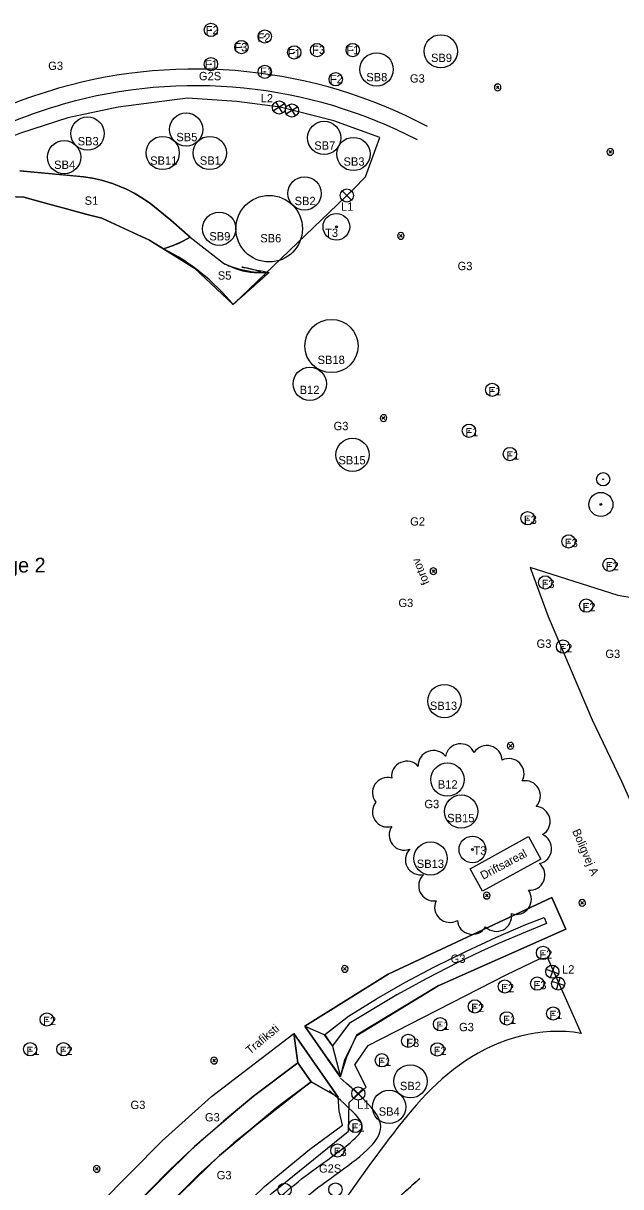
# Model space of a CAD drawing. Extents: x 0 to 512122, y 0 to 6212554.
# Drawn here: x 511504.4 to 511594.1, y 6211506.3 to 6211681 of the extents above; entities that cross this region are included whole.
import ezdxf

# ---------------------------------------------------------------- set-up
doc = ezdxf.new("R2010")
doc.units = 0
for name, color, linetype in [('_G3S_Slået græsser', 7, 'Continuous'), ('_lights', 7, 'Continuous'), ('_Låge L1', 7, 'Continuous'), ('_Låge L2', 7, 'Continuous'), ('_ny fruit trees', 7, 'Continuous'), ('_Paths', 7, 'Continuous'), ('_S1_rabarber', 7, 'Continuous'), ('_S5_spansk kørvel', 7, 'Continuous'), ('_solitaire tree_ K3', 7, 'Continuous'), ('Clouds', 7, 'Continuous'), ('L40 jord udlagt muld og grøft', 7, 'Continuous'), ('MatrikelnummerMaster', 7, 'Continuous'), ('Pumpstation', 7, 'Continuous'), ('Skel', 7, 'Continuous'), ('TV_U_AFM_Symbl_Gul', 7, 'Continuous'), ('TV_U_LYS_Ledn-ror', 7, 'Continuous'), ('TV_U_LYS_Mastenummer', 7, 'Continuous'), ('TV_U_LYS_Nyx330-Trafiksti-x2', 7, 'Continuous')]:
    doc.layers.add(name, color=color, linetype=linetype)

# ---------------------------------------------------------------- blocks, each defined once
blk = doc.blocks.new('SOLITAIRE TREES')
at = {"layer": 'Skel'}
for radius in [2, 0.141]:
    blk.add_circle((0, 0), radius, dxfattribs=at)

msp = doc.modelspace()

# ---------------------------------------------------------------- linework, layer by layer
at = {"layer": '_G3S_Slået græsser'}
msp.add_arc((511599.73, 6211577.45), 18.3, 247.4746, 247.4746, dxfattribs=at)
at = {"layer": '_lights'}
for p, q in [((511575.44, 6211671.6), (511575.84, 6211671.2)), ((511575.84, 6211671.6), (511575.45, 6211671.21)), ((511592.35, 6211661.9), (511592.75, 6211661.51)), ((511592.75, 6211661.9), (511592.36, 6211661.51)), ((511560.9, 6211649.28), (511561.3, 6211648.89)), ((511561.3, 6211649.28), (511560.91, 6211648.89)), ((511558.29, 6211621.94), (511558.69, 6211621.54)), ((511558.69, 6211621.94), (511558.3, 6211621.55)), ((511566.18, 6211598.93), (511565.78, 6211598.53)), ((511565.78, 6211598.92), (511566.17, 6211598.53)), ((511577.37, 6211572.72), (511577.77, 6211572.32)), ((511577.77, 6211572.72), (511577.38, 6211572.33)), ((511574.19, 6211550.21), (511573.79, 6211549.82)), ((511573.79, 6211550.21), (511574.18, 6211549.82)), ((511588.14, 6211549.12), (511588.54, 6211548.72)), ((511588.54, 6211549.12), (511588.15, 6211548.73)), ((511552.88, 6211539.2), (511552.49, 6211538.81)), ((511552.49, 6211539.2), (511552.88, 6211538.8)), ((511533.25, 6211525.43), (511532.85, 6211525.04)), ((511532.85, 6211525.43), (511533.24, 6211525.03)), ((511515.23, 6211509.16), (511515.63, 6211508.76)), ((511515.63, 6211509.16), (511515.24, 6211508.77))]:
    msp.add_line(p, q, dxfattribs=at)
for centre, start, end in [((511575.64, 6211671.4), 315.5636, 315), ((511575.64, 6211671.4), 315, 315.5636), ((511592.55, 6211661.7), 315.5636, 315), ((511592.55, 6211661.7), 315, 315.5636), ((511561.1, 6211649.08), 315.5636, 315), ((511561.1, 6211649.08), 315, 315.5636), ((511558.49, 6211621.74), 315.5636, 315), ((511558.49, 6211621.74), 315, 315.5636), ((511565.98, 6211598.73), 315.5636, 315), ((511565.98, 6211598.73), 315, 315.5636), ((511577.57, 6211572.52), 315.5636, 315), ((511577.57, 6211572.52), 315, 315.5636), ((511573.99, 6211550.01), 315.5636, 315), ((511573.99, 6211550.01), 315, 315.5636), ((511588.34, 6211548.92), 315.5636, 315), ((511588.34, 6211548.92), 315, 315.5636), ((511552.68, 6211539), 315.5636, 315), ((511552.68, 6211539), 315, 315.5636), ((511533.05, 6211525.23), 315.5636, 315), ((511533.05, 6211525.23), 315, 315.5636), ((511515.43, 6211508.96), 315.5636, 315), ((511515.43, 6211508.96), 315, 315.5636)]:
    msp.add_arc(centre, 0.5, start, end, dxfattribs=at)
at = {"layer": '_Låge L1'}
for p, q in [((511553.69, 6211655.85), (511552.29, 6211654.45)), ((511552.29, 6211655.85), (511553.69, 6211654.45)), ((511555.41, 6211521), (511554.01, 6211519.6)), ((511554.01, 6211521), (511555.41, 6211519.6))]:
    msp.add_line(p, q, dxfattribs=at)
for centre in [(511552.99, 6211655.15), (511554.71, 6211520.3)]:
    msp.add_circle(centre, 0.989, dxfattribs=at)
at = {"layer": '_Låge L2'}
for p, q in [((511543.65, 6211668.9), (511541.97, 6211667.86)), ((511542.29, 6211669.22), (511543.33, 6211667.54)), ((511545.59, 6211668.44), (511543.91, 6211667.4)), ((511544.23, 6211668.76), (511545.27, 6211667.08)), ((511584.15, 6211539.53), (511583.52, 6211537.65)), ((511584.77, 6211538.28), (511582.9, 6211538.9)), ((511585.04, 6211537.74), (511584.42, 6211535.86)), ((511585.67, 6211536.49), (511583.79, 6211537.11))]:
    msp.add_line(p, q, dxfattribs=at)
for centre in [(511542.81, 6211668.38), (511544.75, 6211667.92), (511583.84, 6211538.59), (511584.73, 6211536.8)]:
    msp.add_circle(centre, 0.989, dxfattribs=at)
at = {"layer": '_ny fruit trees'}
for centre, radius in [((511532.59, 6211680.02), 1), ((511532.59, 6211680.02), 0.0426), ((511540.67, 6211679.04), 1), ((511540.67, 6211679.04), 0.0426), ((511537.16, 6211677.44), 1), ((511537.16, 6211677.44), 0.0426), ((511545.1, 6211676.65), 1), ((511548.52, 6211677), 1), ((511548.52, 6211677), 0.0426), ((511553.87, 6211677), 1), ((511553.87, 6211677), 0.0426), ((511532.59, 6211674.88), 1), ((511545.1, 6211676.65), 0.0426), ((511532.59, 6211674.88), 0.0426), ((511540.67, 6211673.73), 1), ((511540.67, 6211673.73), 0.0426), ((511551.32, 6211672.61), 1), ((511551.32, 6211672.61), 0.0426), ((511574.82, 6211625.97), 1), ((511574.82, 6211625.97), 0.0426), ((511571.33, 6211619.83), 1), ((511571.33, 6211619.83), 0.0426), ((511577.48, 6211616.33), 1), ((511577.48, 6211616.33), 0.0426), ((511591.48, 6211612.54), 1), ((511591.48, 6211612.54), 0.0426), ((511580.14, 6211606.69), 1), ((511580.14, 6211606.69), 0.0426), ((511586.29, 6211603.2), 1), ((511586.29, 6211603.2), 0.0426), ((511592.43, 6211599.71), 1), ((511592.43, 6211599.71), 0.0426), ((511582.79, 6211597.05), 1), ((511582.79, 6211597.05), 0.0426), ((511588.94, 6211593.56), 1), ((511588.94, 6211593.56), 0.0426), ((511585.45, 6211587.41), 1), ((511585.45, 6211587.41), 0.0426), ((511582.45, 6211541.41), 1), ((511582.45, 6211541.41), 0.0426), ((511576.72, 6211536.36), 1), ((511581.58, 6211536.79), 1), ((511576.72, 6211536.36), 0.0426), ((511581.58, 6211536.79), 0.0426), ((511572.22, 6211533.37), 1), ((511507.94, 6211531.41), 1), ((511572.22, 6211533.37), 0.0426), ((511577, 6211531.58), 1), ((511583.97, 6211532.31), 1), ((511583.97, 6211532.31), 0.0426), ((511507.94, 6211531.41), 0.0426), ((511566.99, 6211530.7), 1), ((511566.99, 6211530.7), 0.0426), ((511577, 6211531.58), 0.0426), ((511562.22, 6211528.2), 1), ((511505.44, 6211526.94), 1), ((511505.44, 6211526.94), 0.0426), ((511510.44, 6211526.94), 1), ((511510.44, 6211526.94), 0.0426), ((511562.22, 6211528.2), 0.0426), ((511566.58, 6211526.91), 1), ((511566.58, 6211526.91), 0.0426), ((511558.25, 6211525.28), 1), ((511558.25, 6211525.28), 0.0426), ((511554.25, 6211515.42), 1), ((511554.25, 6211515.42), 0.0426), ((511551.58, 6211511.73), 1), ((511551.58, 6211511.73), 0.0426), ((511543.64, 6211505.83), 1), ((511551.28, 6211505.87), 1)]:
    msp.add_circle(centre, radius, dxfattribs=at)
at = {"layer": '_Paths'}
for centre, radius, start, end in [((511530.28, 6211599.47), 74.68, 62.1867, 105.9873), ((511530.83, 6211597.57), 76.66, 105.9873, 117.7388), ((511530.28, 6211599.47), 72.18, 62.5002, 105.9889), ((511530.83, 6211597.57), 74.16, 105.9889, 117.6767)]:
    msp.add_arc(centre, radius, start, end, dxfattribs=at)
for points in [[(511533.83, 6211491.3), (511535.62, 6211493.43), (511540.82, 6211499.61), (511548.51, 6211506.42), (511560.79, 6211514.38), (511556.94, 6211518.3), (511552.05, 6211522.6)], [(511531.91, 6211492.91), (511533.7, 6211495.04), (511539.03, 6211501.36), (511546.99, 6211508.41), (511556.86, 6211514.81), (511555.22, 6211516.48), (511550.4, 6211520.72)]]:
    msp.add_open_spline(points, degree=3, dxfattribs=at)
at = {"layer": '_S1_rabarber'}
for points in [[(511503.91, 6211658.84), (511512.53, 6211658.04), (511513.47, 6211657.95), (511514.8, 6211657.74), (511516.14, 6211657.45), (511517.81, 6211656.96), (511518.83, 6211656.57), (511519.91, 6211656.1), (511521.06, 6211655.51), (511522.47, 6211654.68), (511523.56, 6211653.91), (511526.54, 6211651.43), (511529.47, 6211648.88), (511528.45, 6211648.34), (511528.16, 6211648.19), (511526.89, 6211647.66), (511525.45, 6211647.16), (511523.82, 6211648.17), (511523.38, 6211648.45), (511519.78, 6211650.09), (511516.18, 6211651.73), (511513.82, 6211652.37), (511510.34, 6211653.31), (511508.07, 6211653.93), (511504.51, 6211654.89), (511503.34, 6211654.98)], [(511528.45, 6211648.34), (511529.47, 6211648.88), (511526.54, 6211651.43), (511523.56, 6211653.91), (511522.47, 6211654.68), (511521.06, 6211655.51), (511519.91, 6211656.1), (511518.83, 6211656.57), (511517.81, 6211656.96), (511516.14, 6211657.45), (511514.8, 6211657.74), (511513.47, 6211657.95), (511503.91, 6211658.84)], [(511503.34, 6211654.98), (511504.51, 6211654.89), (511508.07, 6211653.93), (511510.34, 6211653.31), (511513.82, 6211652.37), (511516.18, 6211651.73), (511523.38, 6211648.45), (511523.82, 6211648.17), (511525.45, 6211647.16), (511526.89, 6211647.66), (511527.75, 6211648.02)]]:
    msp.add_lwpolyline(points, dxfattribs=at)
msp.add_arc((511519.16, 6211667.38), 21.18, 293.9173, 296.0104, dxfattribs=at)
at = {"layer": '_S5_spansk kørvel'}
msp.add_lwpolyline([(511528.45, 6211648.34), (511529.47, 6211648.88), (511534.47, 6211644.98)], dxfattribs=at)
msp.add_lwpolyline([(511528.45, 6211648.34), (511529.47, 6211648.88), (511534.47, 6211644.98)], dxfattribs=at)
for centre, radius, start, end in [((511519.16, 6211667.38), 21.18, 287.3435, 296.0104), ((511519.16, 6211667.38), 21.18, 287.3435, 296.0104), ((511510.3, 6211617.56), 33.27, 39.6315, 62.8574), ((511510.3, 6211617.56), 33.27, 39.6315, 62.8574), ((512757.67, 6210270.09), 1834.66, 131.5276, 131.75358), ((512757.67, 6210270.09), 1834.66, 131.5276, 131.75358)]:
    msp.add_arc(centre, radius, start, end, dxfattribs=at)
for points in [[(511534.47, 6211644.98), (511536.61, 6211644.07), (511539.36, 6211643.58), (511541.33, 6211643.58), (511534.47, 6211644.98), (511541.33, 6211643.58)], [(511534.47, 6211644.98), (511535.17, 6211644.65), (511536.72, 6211643.91), (511539.09, 6211643.53), (511540.67, 6211643.57), (511541.33, 6211643.58)]]:
    msp.add_open_spline(points, degree=3, dxfattribs=at)
at = {"layer": '_solitaire tree_ K3'}
for radius in [1.81, 0.127]:
    msp.add_circle((511591.14, 6211608.76), radius, dxfattribs=at)
at = {"layer": 'Clouds'}
for centre, start, end in [((511570.05, 6211570.54), 25.2077, 170.2077), ((511574.02, 6211570.27), 2.0157, 147.0157), ((511565.99, 6211569.54), 37.6761, 182.6761), ((511577.32, 6211568.31), 331.608, 116.608), ((511562, 6211567.92), 41.3523, 186.3523), ((511559.11, 6211565.48), 74.1952, 219.1952), ((511579.78, 6211564.99), 316.3178, 101.3178), ((511559.12, 6211562.6), 140.8408, 285.8408), ((511581.24, 6211561.14), 300.1916, 85.1916), ((511561.62, 6211559.11), 145.6596, 290.6596), ((511581.47, 6211557.08), 281.4375, 66.4375), ((511564.07, 6211555.4), 135.9748, 280.9748), ((511580.45, 6211553.1), 264.8625, 49.8625), ((511566.06, 6211551.49), 133.096, 278.096), ((511578.42, 6211549.47), 251.5454, 36.5454), ((511568.45, 6211548.27), 154.9974, 299.9974), ((511571.86, 6211546.47), 184.528, 329.528), ((511575.45, 6211546.92), 224.7551, 9.7551)]:
    msp.add_arc(centre, 2.28, start, end, dxfattribs=at)
at = {"layer": 'L40 jord udlagt muld og grøft'}
for points in [[(511585.89, 6211544.95), (511566.7, 6211536.46), (511554.44, 6211529.04), (511552.92, 6211525.74), (511551.99, 6211522.79), (511549.8, 6211525.95), (511546.66, 6211530.43), (511559.18, 6211538.24), (511583.79, 6211549.72)], [(511583.79, 6211549.72), (511559.18, 6211538.24), (511546.66, 6211530.43), (511549.8, 6211525.95), (511552.02, 6211522.81), (511552.71, 6211525.38), (511554.49, 6211529.02), (511566.7, 6211536.46), (511585.89, 6211544.95)], [(511582.63, 6211546.75), (511582.99, 6211545.81), (511579.82, 6211544.54), (511575.77, 6211542.81), (511573.1, 6211541.6), (511569.57, 6211539.91), (511565.01, 6211537.58), (511560.5, 6211535.11), (511553.32, 6211530.82), (511550.83, 6211527.45), (511549.66, 6211529.1), (511553.25, 6211531.93), (511557.45, 6211534.49), (511561.72, 6211536.94), (511566.06, 6211539.26), (511570.95, 6211541.69), (511575.37, 6211543.72), (511579.89, 6211545.65)], [(511546.66, 6211530.43), (511549.67, 6211529.11), (511550.85, 6211527.41), (511552.03, 6211522.78)], [(511519.91, 6211502.22), (511515.82, 6211503.61), (511525.25, 6211513.18), (511532.69, 6211519.82), (511545.02, 6211529.29), (511545.61, 6211524.88), (511539, 6211519.89), (511530.1, 6211512.31)], [(511545.02, 6211529.29), (511551.71, 6211519.74), (511547.65, 6211522.04), (511545.61, 6211524.88)], [(511519.91, 6211502.22), (511526.42, 6211508.85), (511529.16, 6211511.45), (511534.45, 6211516.15), (511539, 6211519.89), (511545.61, 6211524.88), (511547.65, 6211522.04), (511542.47, 6211518.17), (511533.87, 6211511), (511522.58, 6211499.95)], [(511525.32, 6211495.05), (511526.64, 6211494.9), (511528.4, 6211494.46), (511540.64, 6211506.35), (511547.4, 6211511.86), (511552.32, 6211515.55), (511551.86, 6211517.68), (511551.71, 6211519.73), (511547.63, 6211522.03), (511536.03, 6211512.89), (511531.05, 6211508.43), (511522.58, 6211499.95)]]:
    msp.add_lwpolyline(points, close=True, dxfattribs=at)
for points in [[(511546.66, 6211530.43), (511549.67, 6211529.11), (511550.85, 6211527.41), (511552.03, 6211522.78), (511546.66, 6211530.43)], [(511545.61, 6211524.88), (511547.65, 6211522.04), (511551.71, 6211519.74), (511545.02, 6211529.29), (511545.61, 6211524.88)], [(511519.91, 6211502.22), (511522.58, 6211499.95), (511533.87, 6211511), (511542.47, 6211518.17), (511547.65, 6211522.04), (511545.61, 6211524.88), (511539, 6211519.89), (511534.45, 6211516.15), (511529.16, 6211511.45), (511526.42, 6211508.85), (511519.91, 6211502.22), (511522.58, 6211499.95)]]:
    msp.add_lwpolyline(points, dxfattribs=at)
at = {"layer": 'MatrikelnummerMaster'}
msp.add_lwpolyline([(511553.97, 6211656.1), (511555.79, 6211657.96), (511557.93, 6211663.87), (511551.03, 6211666.35), (511543, 6211668.4), (511536.48, 6211669.29), (511529.07, 6211669.77), (511518.64, 6211668.43), (511511.1, 6211666.82), (511503.97, 6211664.54), (511497.17, 6211661.84), (511493.04, 6211660.13), (511486.68, 6211657.15), (511484.32, 6211654.41), (511495.49, 6211655.44), (511504.51, 6211654.89), (511516.18, 6211651.73), (511523.38, 6211648.45), (511530.14, 6211644.26), (511535.92, 6211638.78)], close=True, dxfattribs=at)
msp.add_lwpolyline([(511519.3, 6211478.52), (511512.13, 6211482.26), (511517.84, 6211488.88), (511521.98, 6211493.75), (511526.06, 6211494.09), (511530.02, 6211493.42), (511541.67, 6211505.27), (511553.25, 6211514.63), (511553.34, 6211518.92), (511555.87, 6211521.24), (511554.18, 6211524.58), (511556.19, 6211527.5), (511577, 6211538.18), (511581.94, 6211540.5), (511583.12, 6211540.67), (511588.16, 6211529.31)], dxfattribs=at)
msp.add_open_spline([(511588.16, 6211529.31), (511582.04, 6211530.43), (511569.5, 6211526.54), (511558.5, 6211512.66), (511548.44, 6211498.44), (511543.23, 6211488.47), (511531.73, 6211479.28), (511527.73, 6211474.95), (511588.16, 6211529.31), (511527.73, 6211474.95)], degree=3, dxfattribs=at)
at = {"layer": 'Pumpstation'}
msp.add_lwpolyline([(511571.49, 6211554.05), (511580.27, 6211558.87), (511582.1, 6211555.5), (511573.34, 6211550.69), (511571.49, 6211554.05)], dxfattribs=at)
at = {"layer": 'TV_U_LYS_Mastenummer'}
for centre, radius in [((511567.1, 6211676.81), 2.5), ((511567.1, 6211676.81), 2.5), ((511557.46, 6211674.09), 2.5), ((511557.46, 6211674.09), 2.5), ((511514.06, 6211664.45), 2.5), ((511514.06, 6211664.45), 2.5), ((511528.87, 6211665.07), 2.5), ((511528.87, 6211665.07), 2.5), ((511549.59, 6211663.8), 2.5), ((511549.59, 6211663.8), 2.5), ((511510.53, 6211660.91), 2.5), ((511510.53, 6211660.91), 2.5), ((511525.34, 6211661.54), 2.5), ((511525.34, 6211661.54), 2.5), ((511532.41, 6211661.54), 2.5), ((511532.41, 6211661.54), 2.5), ((511553.98, 6211661.39), 2.5), ((511553.98, 6211661.39), 2.5), ((511546.64, 6211655.47), 2.5), ((511546.64, 6211655.47), 2.5), ((511541.33, 6211650.17), 5), ((511541.33, 6211650.17), 5), ((511533.83, 6211650.17), 2.5), ((511533.83, 6211650.17), 2.5), ((511550.68, 6211632.55), 4), ((511550.68, 6211632.55), 4), ((511547.42, 6211626.87), 2.5), ((511547.42, 6211626.87), 2.5), ((511553.85, 6211616.21), 2.5), ((511553.85, 6211616.21), 2.5), ((511567.64, 6211579.23), 2.5), ((511567.64, 6211579.23), 2.5), ((511568.1, 6211567.43), 2.5), ((511568.1, 6211567.43), 2.5), ((511570.16, 6211562.64), 2.5), ((511565.57, 6211555.59), 2.5), ((511562.53, 6211522.12), 2.5), ((511562.53, 6211522.12), 2.5), ((511559.33, 6211518.28), 2.5), ((511559.33, 6211518.28), 2.5)]:
    msp.add_circle(centre, radius, dxfattribs=at)
at = {"layer": 'TV_U_LYS_Nyx330-Trafiksti-x2'}
msp.add_lwpolyline([(511597.63, 6211559.52), (511613.16, 6211564.28), (511614.77, 6211563.81), (511623.67, 6211565.57), (511625.54, 6211567.12), (511626.88, 6211569.29), (511627.71, 6211571.47), (511628.18, 6211574.42), (511628.13, 6211576.38), (511625.9, 6211578.04), (511621.09, 6211580.99), (511612.59, 6211585.69), (511610.51, 6211589.45), (511606.94, 6211592.12), (511604.04, 6211593.64), (511600.52, 6211593.88), (511593.75, 6211595.09), (511580.53, 6211599.31), (511583.21, 6211591.92), (511589.82, 6211576.39), (511594.25, 6211567.21)], close=True, dxfattribs=at)

# ---------------------------------------------------------------- block references
at = {"layer": 'Skel'}
for p in [(511551.42, 6211650.46), (511571.84, 6211556.94)]:
    msp.add_blockref('SOLITAIRE TREES', p, dxfattribs=at)

# ---------------------------------------------------------------- texts
at = {"layer": 'TV_U_AFM_Symbl_Gul'}
for s, p in [('F2', (511531.8, 6211679.36)), ('F2', (511539.58, 6211678.24)), ('F3', (511536.1, 6211676.8)), ('F1', (511544.13, 6211675.89)), ('F3', (511547.78, 6211676.4)), ('F1', (511552.91, 6211676.38)), ('G3', (511508.15, 6211674.01)), ('F1', (511531.67, 6211674.23)), ('SB9', (511565.63, 6211675.21)), ('G2S', (511530.78, 6211672.47)), ('F1', (511539.97, 6211673.13)), ('SB8', (511555.91, 6211672.31)), ('F2', (511550.44, 6211672.02)), ('G3', (511562.46, 6211672.11)), ('L2', (511540.05, 6211669.14)), ('SB3', (511512.57, 6211662.69)), ('SB5', (511527.39, 6211663.31)), ('SB7', (511548.1, 6211662.04)), ('SB4', (511509.04, 6211659.15)), ('SB11', (511523.46, 6211659.78)), ('SB1', (511530.92, 6211659.78)), ('SB3', (511552.49, 6211659.63)), ('S1', (511513.62, 6211653.76)), ('SB2', (511545.15, 6211653.71)), ('L1', (511552.11, 6211652.86)), ('SB9', (511532.35, 6211648.41)), ('SB6', (511539.99, 6211648.12)), ('T3', (511549.72, 6211648.93)), ('G3', (511569.62, 6211643.94)), ('S5', (511533.62, 6211642.52)), ('SB18', (511548.6, 6211629.85)), ('B12', (511545.9, 6211625.34)), ('F1', (511574.27, 6211625.13)), ('G3', (511551, 6211619.91)), ('F1', (511570.78, 6211618.98)), ('SB15', (511551.73, 6211614.78)), ('F1', (511576.93, 6211615.49)), ('G2', (511562.5, 6211605.58)), ('F3', (511579.58, 6211605.84)), ('F3', (511585.73, 6211602.35)), ('F2', (511591.88, 6211598.86)), ('F3', (511582.24, 6211596.2)), ('G3', (511560.74, 6211593.35)), ('F2', (511588.39, 6211592.71)), ('G3', (511581.48, 6211587.23)), ('F2', (511584.9, 6211586.56)), ('G3', (511591.81, 6211585.7)), ('SB13', (511565.46, 6211577.9)), ('B12', (511566.65, 6211566.09)), ('G3', (511564.64, 6211563.14)), ('SB15', (511568.06, 6211561.04)), ('T3', (511571.99, 6211556.16)), ('SB13', (511563.5, 6211554.17)), ('G3', (511568.58, 6211539.91)), ('F2', (511581.89, 6211540.56)), ('L2', (511585.3, 6211538.31)), ('F2', (511576.17, 6211535.51)), ('F3', (511581.02, 6211535.95)), ('F2', (511571.67, 6211532.52)), ('F1', (511583.42, 6211531.46)), ('F2', (511507.38, 6211530.56)), ('F1', (511566.43, 6211529.85)), ('G3', (511569.84, 6211529.65)), ('F1', (511576.45, 6211530.73)), ('F3', (511561.91, 6211527.27)), ('F1', (511504.88, 6211526.09)), ('F2', (511509.88, 6211526.09)), ('F2', (511566.02, 6211526.07)), ('F1', (511557.7, 6211524.43)), ('SB2', (511560.96, 6211520.8)), ('G3', (511520.51, 6211517.96)), ('L1', (511554.55, 6211518)), ('SB4', (511557.78, 6211516.96)), ('G3', (511531.68, 6211516.1)), ('F1', (511553.7, 6211514.57)), ('F3', (511551.03, 6211510.89)), ('G2S', (511548.81, 6211508.4)), ('G3', (511533.45, 6211507.4))]:
    msp.add_text(s, height=1.25, dxfattribs=at).set_placement(p)
for s, rotation, p in [('fortov', 112.1612, (511565.43, 6211596.97)), ('Boligvej A', 293.3172, (511586.8, 6211559.71)), ('Driftsareal', 28.0622, (511573.45, 6211552.37)), ('Trafiksti', 39.7394, (511538.46, 6211526.1))]:
    msp.add_text(s, height=1.25, rotation=rotation, dxfattribs=at).set_placement(p)
at = {"layer": 'TV_U_LYS_Ledn-ror'}
msp.add_text('Klynge 2', height=2.219, dxfattribs=at).set_placement((511496.21, 6211598.54))

doc.saveas('drawing.dxf')
